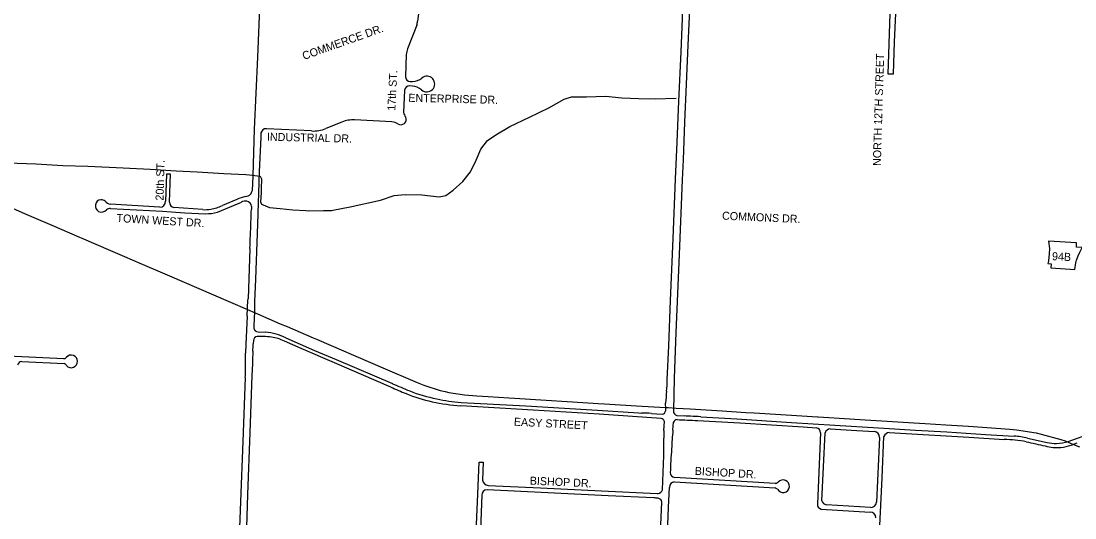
# Model space of a CAD drawing. Extents: x 0 to 712119, y 0 to 761125.
# Drawn here: x 679749 to 686331, y 739583 to 742682 of the extents above; entities that cross this region are included whole.
import ezdxf

# ---------------------------------------------------------------- set-up
doc = ezdxf.new("R2010")
doc.units = 0
for name, color, linetype in [('Arkansas-Missouri Railroad', 7, 'Continuous'), ('HWY signs', 7, 'Continuous'), ('PAVED ROADS', 7, 'Continuous'), ('stream or creek', 7, 'Continuous'), ('street names', 7, 'Continuous')]:
    doc.layers.add(name, color=color, linetype=linetype)

msp = doc.modelspace()

# ---------------------------------------------------------------- linework, layer by layer
at = {"layer": 'Arkansas-Missouri Railroad'}
msp.add_lwpolyline([(679573.3, 741568.6), (679756.6, 741488.7), (679756.6, 741488.7), (679829.5, 741456.9), (679940.2, 741409.4), (679940.2, 741409.4), (680114.7, 741334.5), (680124, 741330.5), (680124, 741330.5), (680307.8, 741251.5), (680307.8, 741251.5), (680395.4, 741213.9), (680491.5, 741172.4), (680491.5, 741172.4), (680632.6, 741111.5), (680675.1, 741093.3), (680675.1, 741093.3), (680858.9, 741014.2), (680858.9, 741014.2), (681042.6, 740935.2), (681042.6, 740935.2), (681072.2, 740922.5), (681226.3, 740856.1), (681226.3, 740856.1), (681368.1, 740795), (681410, 740777), (681410, 740777), (681573.6, 740706.7), (681593.7, 740698), (681593.7, 740698), (681777.4, 740619), (681777.4, 740619), (681796.4, 740610.9), (681839.8, 740592.1), (681839.8, 740592.1), (682022.8, 740513.1), (682023.4, 740512.8), (682023.4, 740512.8), (682207.2, 740434.1), (682207.2, 740434.1), (682223, 740427.3), (682264.2, 740411), (682366.3, 740379.1), (682397, 740371.7), (682397, 740371.7), (682420.3, 740366.1), (682518.1, 740350.9), (682595, 740345.3), (682595, 740345.3), (682666.4, 740340.1), (682794.6, 740331.9), (682794.6, 740331.9), (682830, 740329.6), (682994.2, 740319.6), (682994.2, 740319.6), (683193.8, 740307.4), (683193.8, 740307.4), (683352.4, 740297.7), (683393.5, 740295.2), (683393.5, 740295.2), (683593.1, 740283.3), (683593.1, 740283.3), (683774.8, 740272.4), (683792.8, 740271.3), (683839.7, 740268.2), (683928, 740262.8), (683928, 740262.8), (684127.6, 740250.6), (684275.8, 740241.6), (684327.2, 740238.4), (684327.2, 740238.4), (684526.9, 740226), (684526.9, 740226), (684722.5, 740213.8), (684726.5, 740213.6), (684726.5, 740213.6), (684926.1, 740200.9), (684926.1, 740200.9), (685021.2, 740194.8), (685125.7, 740188.5), (685125.7, 740188.5), (685325.4, 740176.5), (685325.4, 740176.5), (685396.6, 740172.2), (685525, 740164.3), (685525, 740164.3), (685666.7, 740155.5), (685724.6, 740151.2), (685724.6, 740151.2), (685924, 740136.2), (685924, 740136.2), (685966.8, 740133), (686088.3, 740113.3), (686121.2, 740104.8), (686121.2, 740104.8), (686243.2, 740073.2), (686269.5, 740064), (686312, 740045.9), (686312, 740045.9), (686358.8, 740026)], dxfattribs=at)
at = {"layer": 'HWY signs'}
msp.add_lwpolyline([(686330, 741133.6), (686336.5, 741173.9), (686341.1, 741191.6), (686351.4, 741218.4), (686362.1, 741240.8), (686376.9, 741269.9), (686340, 741272.1), (686341.6, 741299.5), (686166.2, 741310.1), (686171.6, 741264.5), (686171, 741231.4), (686165.5, 741187.1), (686162.6, 741169.5), (686182.8, 741168.3), (686181.2, 741142.5)], close=True, dxfattribs=at)
at = {"layer": 'PAVED ROADS'}
for points in [[(681241.5, 742903.5), (681237.5, 742762.5), (681224.6, 742457.9), (681205.5, 742007.5), (681195.5, 741718.1), (681191.8, 741624.5)], [(682241.5, 742852.5), (682241, 742840), (682239.5, 742791), (682225.5, 742682.5)], [(683785.1, 740443.9), (683794.4, 740656), (683805.6, 740938.7), (683821.9, 741325.4), (683837.2, 741697), (683846.6, 741927), (683856.5, 742183.3), (683871.4, 742491.8), (683879.1, 742699.6), (683877.8, 742771.2)], [(683923.9, 742751), (683919, 742666.2), (683913.5, 742531.5), (683903.1, 742289.8), (683892.5, 742052.7), (683883.4, 741818.1), (683877.2, 741692.6), (683859.7, 741227.4), (683839.3, 740739.8), (683828.1, 740454.1), (683823, 740251.5)], [(685209.4, 742729.8), (685201.3, 742554.2), (685194.9, 742350.9), (685164.2, 742350.9), (685176.9, 742729.1)], [(682220.5, 742657.5), (682163, 742510.5)], [(682155, 742473.5), (682148.9, 742335.7)], [(682193.6, 742277.5), (682175.4, 742279)], [(682180.1, 742306.2), (682194.5, 742305.6)], [(682144.6, 742251.2), (682138.3, 742112.5)], [(682064.9, 742055.1), (681832.2, 742066.7)], [(681562.9, 741997.1), (681281.8, 742011.4)], [(681753, 742052.7), (681652.6, 742012.4)], [(681247, 741986.1), (681245.7, 741959.4), (681236.8, 741742.4), (681225, 741415.5), (681212.1, 741071.8), (681206.9, 740933.7)], [(680676.5, 741552.7), (680682.6, 741726.7), (680657.6, 741727.1), (680651.7, 741558.3)], [(680614.9, 741521.8), (680304.7, 741539.7)], [(680975.9, 741490.4), (681124.6, 741553.1)], [(681095.7, 741569.1), (681006.3, 741532.1)], [(680307.3, 741512.7), (680632.9, 741495.9), (680771.2, 741486.4), (680900.5, 741480.4)], [(680884.7, 741506.7), (680703.6, 741518.7)], [(681187.9, 741526.1), (681187.6, 741509.8)], [(681178.3, 741263.7), (681166.3, 740950.9)], [(681160.1, 740840.8), (681153.5, 740667.7), (681151.4, 740611.1)], [(681205.5, 740839), (681202.9, 740769.1)], [(681199.8, 740690.3), (681199.2, 740670.1)], [(681263.5, 740715), (681223.3, 740715.3)], [(681229, 740744), (681276.2, 740741.5)], [(682058, 740399.7), (681707.4, 740551.2), (681497.4, 740641), (681393.8, 740685.8)], [(681402.9, 740706.6), (681582.1, 740627.5), (681717.4, 740571.2), (682068.3, 740420.8)], [(680015.7, 740576.5), (678609.7, 740642)], [(679753.2, 740559.4), (680017.5, 740546.9)], [(681193.4, 740545.4), (681189.4, 740470.8), (681178.6, 740115.8), (681164, 739728.5), (681154.5, 739456), (681143, 739133), (681138.3, 739066.4), (681128.7, 738808.9), (681119.5, 738567.2), (681106.1, 738236.1), (681099.6, 738035.4), (681095.2, 737815.6)], [(681149.4, 740459.9), (681133.6, 740059.5), (681119.2, 739686.1), (681100.7, 739194.2), (681086.2, 738792.9), (681071.7, 738400.7), (681059.7, 738083.5), (681059.7, 738083.5), (681057.1, 738016.3), (681053, 737936.7)], [(682497, 740304.3), (682901.8, 740282), (683349.7, 740254.9), (683605.9, 740238), (683623.4, 740237.3)], [(683746.7, 740204.3), (683360.4, 740230.4), (682948.1, 740255.6), (682494.8, 740283.4)], [(683685.5, 740234.5), (683752.9, 740230.9)], [(683763.8, 740129.5), (683766.9, 740185.6)], [(683820.2, 740131.6), (683823.2, 740180.1)], [(683845.4, 740222), (683894.8, 740219.1)], [(683974.2, 740191.2), (684237.2, 740175.5), (684634.5, 740150.5), (684716.2, 740145.3)], [(683994.4, 740214.3), (684218.9, 740200.5), (684560.3, 740179.2), (684831.7, 740162.4), (685104.6, 740145.7), (685335.5, 740131.3), (685531.5, 740119.4), (685773, 740103.8), (685951.1, 740093.2)], [(684742.8, 740113.1), (684722.5, 739671.9)], [(684750.6, 739690.7), (684771.4, 740113.3)], [(684802.4, 740139.8), (684969.1, 740128.9), (685079.2, 740122.4)], [(685104.8, 739365.5), (685126.5, 739832.4), (685138.5, 740091.5)], [(685171.6, 740116.9), (685241.2, 740112.3), (685668.2, 740086), (685889.3, 740072.6)], [(685171.6, 740116.9), (685171.6, 740116.9)], [(683762.9, 739985.2), (683763.8, 740081.3)], [(685111.1, 740085.8), (685091.8, 739681)], [(686034.1, 740081.8), (686158, 740053.8)], [(686289.5, 740060.8), (686375.6, 740091.1)], [(686307.1, 740037.9), (686345.9, 740051.4)], [(682578.5, 739189), (682590, 739449.5), (682599.5, 739683), (682609.6, 739931.8), (682635.8, 739930.4), (682631.1, 739819.2)], [(683754.8, 739758.6), (683761.2, 739921)], [(684458.5, 739798.5), (683830.3, 739834.8)], [(682665.6, 739785.7), (682992.5, 739770.3), (683374.7, 739751.3), (683721, 739735), (683728.5, 739735)], [(683785, 739433), (683793.5, 739649.5), (683799.8, 739773.9)], [(683830.4, 739808.6), (684458.1, 739771.2)], [(682626, 739724.5), (682618.7, 739510.1)], [(683700.5, 739708), (683415, 739721.3), (683038.4, 739739.5), (682659.1, 739758.3)], [(683741.5, 739447), (683751.5, 739682)], [(684745.8, 739638.4), (685051.9, 739620.1)], [(684745.8, 739638.4), (684745.8, 739638.4)], [(685053.6, 739647.9), (684779.7, 739665.3)]]:
    msp.add_lwpolyline(points, dxfattribs=at)
for centre, radius, start, end in [((682088, 742697), 138.3, 343.39999, 353.98015), ((682259.8, 742470.2), 104.9, 157.40041, 178.19865), ((682179.6, 742336.9), 30.7, 182.27132, 270.82701), ((682283.7, 742290.2), 48.9, 227.31787, 130.29657), ((682176.4, 742246.9), 32.1, 91.89284, 172.1747), ((682177, 742155.8), 122.9, 53.23414, 82.24107), ((682191.2, 742401.2), 95.6, 272.01957, 309.61096), ((681824.7, 741877.7), 189.2, 87.72247, 112.27263), ((682120.6, 742069.7), 33.5, 238.05305, 24.29828), ((682198.2, 742121.8), 60.6, 188.81796, 219.19921), ((681279.6, 741977.7), 33.7, 86.30157, 165.51302), ((681574.7, 742197.5), 200.8, 266.63655, 292.81808), ((682048.6, 741950.8), 105.5, 59.04166, 81.13345), ((681153.6, 741628.4), 38.4, 318.76035, 354.06964), ((680248.7, 741531.9), 36, 91.56895, 171.36317), ((680248.3, 741526.6), 41.4, 50.84999, 90.69434), ((680318, 741594.8), 56.6, 219.63344, 256.46484), ((680615, 741558.6), 36.7, 269.80131, 359.61946), ((680710.6, 741552.1), 34.1, 178.9144, 258.12226), ((681237.9, 741266), 334.8, 105.12757, 115.13937), ((681153, 741489.7), 69.6, 85.01228, 114.1253), ((681150.4, 741633.2), 44.1, 270.20533, 316.83696), ((681153, 741524.5), 34.9, 2.52972, 80.05987), ((680252.7, 741530.6), 40.2, 170.40676, 240.90386), ((680251.4, 741531.6), 40.4, 243.28072, 319.83803), ((680302.3, 741482.9), 30.3, 80.54042, 131.37794), ((680899.6, 741660.9), 154.9, 264.47754, 282.63058), ((680894.3, 741816.5), 336.1, 271.06644, 284.05513), ((680884.8, 741798.9), 293.1, 279.53846, 294.47429), ((668306.5, 741933.8), 12888, 357.3848, 358.11456), ((655617.4, 742177.8), 25577.2, 357.9518, 358.13577), ((679528.6, 741027.8), 1639.5, 355.98495, 357.31184), ((671304.3, 741416.2), 9872.6, 356.65921, 357.07849), ((742296.2, 738901.4), 61121.5, 178.125146, 178.183369), ((682020.5, 740932.2), 813.6, 179.89212, 182.19344), ((681229, 740770.1), 26.1, 182.23891, 269.86111), ((681228.5, 740686.9), 28.9, 100.49415, 173.3204), ((681259.5, 740307.6), 407.3, 82.52822, 89.44407), ((681249.1, 740395.8), 346.8, 63.68113, 85.51775), ((681269.9, 740436.1), 278.7, 63.61626, 81.20729), ((686873.3, 740356.1), 5683.1, 177.29499, 178.0912), ((680056, 740713.6), 1144, 355.52543, 357.82259), ((679754.6, 740531.7), 27.8, 92.83807, 170.44325), ((680017.1, 740593.8), 17.3, 265.39338, 331.35401), ((680062.3, 740559.9), 39.4, 221.30288, 139.53717), ((679269, 740587.4), 1882.5, 357.59677, 0.71969), ((680009.9, 740522.6), 25.5, 26.35582, 72.43073), ((680610.8, 740488.9), 539.4, 356.91277, 2.07976), ((685669.6, 748839.7), 9156.9, 246.84021, 247.57225), ((682444.2, 740500.7), 1342.2, 354.58315, 357.57613), ((683712.4, 744125.1), 4076.2, 246.05508, 247.51962), ((682495.1, 741173.1), 883.1, 247.26658, 258.35596), ((682526.2, 741265.9), 956.8, 248.53758, 259.10014), ((685401, 740211.9), 1628.8, 174.29086, 176.91983), ((682572.4, 741492.1), 1211.1, 257.81605, 266.32276), ((682575.4, 741375.4), 1074, 257.62996, 265.81569), ((680862.6, 740250.6), 2912.4, 0.03778, 0.96187), ((683620.5, 739466.5), 770.8, 85.16425, 89.78211), ((683751, 740255), 24.2, 274.50888, 353.94942), ((683852.6, 740250.8), 29.6, 178.62049, 255.91635), ((683742.6, 740179.5), 25.1, 13.86607, 80.4349), ((683849.6, 740167.9), 29.2, 96.63726, 155.0747), ((684187.5, 746531.2), 6343.6, 266.91656, 268.07311), ((683898.2, 739926.3), 292.8, 83.61905, 90.65279), ((683727.2, 735217.5), 5003.9, 86.93887, 87.66872), ((685158.7, 740105.4), 1395.1, 179.01041, 180.98959), ((686144.5, 739906.9), 2335.1, 174.47793, 177.37004), ((684710.2, 740113.3), 32.5, 359.60348, 79.39059), ((684804.9, 740105.4), 34.4, 94.06945, 166.7474), ((685073.9, 740085.5), 37.2, 0.36641, 81.81133), ((685175.8, 740077.2), 39.9, 96.03521, 159.07475), ((685920.7, 739563.3), 530.7, 77.66504, 86.71989), ((685870.2, 739189.8), 883, 79.82393, 88.76466), ((688336.2, 749993.6), 10199.7, 256.91073, 257.5979), ((686217.3, 740280.9), 259.1, 253.92915, 275.91368), ((686205.4, 740248.8), 200.7, 256.30944, 272.95674), ((686198.8, 740373.5), 325.5, 272.99233, 286.17192), ((686225.7, 740244), 221.6, 274.73524, 291.56576), ((683221.5, 739966.7), 541.6, 355.15765, 1.95013), ((687145.1, 739764.2), 3342.7, 175.71323, 178.26158), ((683836, 739866.3), 32.1, 181.231, 259.73175), ((682669.1, 739823.7), 38.2, 186.85928, 264.85429), ((683833.5, 739775.1), 33.7, 95.29454, 182.08841), ((684442.7, 739728.2), 45.7, 48.21565, 70.28987), ((684455, 739834), 35.7, 275.67854, 309.40005), ((684508.2, 739781.1), 39.7, 208.27851, 140.23985), ((682659.7, 739724.6), 33.7, 91.09028, 180.11227), ((683689.2, 739446.4), 261.9, 81.69761, 87.52377), ((683725.8, 739679.7), 25.8, 5.11427, 87.27271), ((683722.5, 739768.2), 33.7, 280.3051, 343.46353), ((684753.5, 739668.6), 31.2, 173.81143, 255.69082), ((684784, 739699.5), 34.5, 194.79298, 262.81201), ((685056.2, 739683.6), 35.7, 265.84362, 355.81917), ((685050.7, 739583.2), 37, 0.34836, 88.11799)]:
    msp.add_arc(centre, radius, start, end, dxfattribs=at)
at = {"layer": 'stream or creek'}
msp.add_lwpolyline([(679663.6, 741799), (679843.3, 741791.2), (680010.5, 741781.9), (680166.7, 741777.2), (680387.1, 741767.8), (680555.8, 741758.4), (680716.7, 741747.5), (680848, 741741.2), (681015.2, 741731.8), (681153.3, 741725.2), (681176.1, 741724.1), (681241.7, 741714.6), (681251.1, 741699), (681248.9, 741637), (681248, 741611.5), (681244.9, 741555.3), (681250.2, 741539.7), (681300.2, 741519.8), (681366.2, 741512.7), (681446.2, 741504.8), (681527.4, 741500.5), (681541.2, 741499.8), (681637.1, 741500.4), (681687.2, 741500.7), (681697, 741502.7), (681804.2, 741523.8), (681994.2, 741565.7), (682078.2, 741594.7), (682147.2, 741601.8), (682251.2, 741598.8), (682360.2, 741586.8), (682402.2, 741594.8), (682448.2, 741627.8), (682508.2, 741681.8), (682555.2, 741742.8), (682591.2, 741814.8), (682621.2, 741883.8), (682661.2, 741937.8), (682714.2, 741973.7), (682801.2, 742024.8), (682925.2, 742083.7), (683045.2, 742141.8), (683141.2, 742194.7), (683187.2, 742209.7), (683280.2, 742209.7), (683400.2, 742214.8), (683500.2, 742202.8), (683604.2, 742199.8), (683709.2, 742196.8), (683841.2, 742201.8)], dxfattribs=at)

# ---------------------------------------------------------------- texts
at = {"layer": 'HWY signs'}
msp.add_text('94B', height=50, rotation=357.01046, dxfattribs=at).set_placement((686187, 741191.7))
at = {"layer": 'street names'}
for s, rotation, p in [('COMMERCE DR.', 19.57274, (681515.8, 742439.6)), ('NORTH 12TH STREET', 88.27311, (685118.6, 741778.3)), ('17th ST.', 86.89213, (682086, 742122.4)), ('ENTERPRISE DR.', 358.63856, (682167, 742179.4)), ('INDUSTRIAL DR.', 358.71076, (681284.1, 741936.5)), ('20th ST.', 88.4127, (680638.4, 741562.4)), ('TOWN WEST DR.', 356.55657, (680343.9, 741429.8)), ('COMMONS DR.', 357.42673, (684126.2, 741444.4)), ('EASY STREET', 357.00786, (682825.9, 740159.2)), ('BISHOP DR.', 356.50928, (683955.4, 739852.5)), ('BISHOP DR.', 357.39354, (682925.2, 739791.3))]:
    msp.add_text(s, height=50, rotation=rotation, dxfattribs=at).set_placement(p)

doc.saveas('drawing.dxf')
